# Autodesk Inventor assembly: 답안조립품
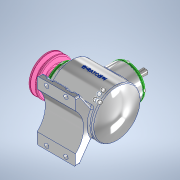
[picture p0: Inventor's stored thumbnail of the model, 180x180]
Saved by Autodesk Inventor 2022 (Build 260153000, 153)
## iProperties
Created: 2023-04
Part Number: 답안조립품
Document SubType Name: Assembly
Designer: Admin
Author: Admin
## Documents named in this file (17)
- C:\Users\Admin\Desktop\730411V1013\답안조립품.iam
- C:\Users\Admin\Desktop\730411V1013\본체.ipt
- C:\Users\Admin\Desktop\730411V1013\커버.ipt
- C:\Users\Admin\Desktop\730411V1013\베어링 6203.ipt
- C:\Users\Admin\Desktop\730411V1013\오일실 17 x 32 x 8.ipt
- C:\Users\Admin\Desktop\730411V1013\메인 축.ipt
- 메인 축.ipt
- C:\Users\Admin\Desktop\730411V1013\키 5 x 5 x 14.ipt
- C:\Users\Admin\Desktop\730411V1013\메인 베벨기어.ipt
- C:\Users\Admin\Desktop\730411V1013\서브 축.ipt
- 서브 축.ipt
- C:\Users\Admin\Desktop\730411V1013\키 4 x 4 x 14.ipt
- C:\Users\Admin\Desktop\730411V1013\서브 베벨기어.ipt
- C:\Users\Admin\Desktop\730411V1013\V-벨트풀리.ipt
- C:\Users\Admin\Desktop\730411V1013\볼트 M4 x 10.ipt
- C:\Users\Admin\Desktop\730411V1013\와셔 4 x 16.ipt
- C:\Users\Admin\Desktop\730411V1013\육각볼트 M4 x 8.ipt
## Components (1 placed, 1 different names)
1. V-벨트풀리:1
